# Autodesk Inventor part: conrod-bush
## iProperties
Created: 2002-08
Part Number: conrod-bush
Document SubType Name: Modeling
Designer: t_munrn
Density: 1 g/cm^3
Control State: 0
Master: False
Checked Out: False
Shininess: 64.0
Length Units: 11269
Angle Units: 11279
Time Units: 11290
Mass Units: 11283
Length Display Precision: 3
Angle Display Precision: 2
Density: 0.0
Volumn: 0.0
Area: 0.0
PropertySet Name: Model Information
Author: t_munrn
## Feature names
1. Extrusion1
